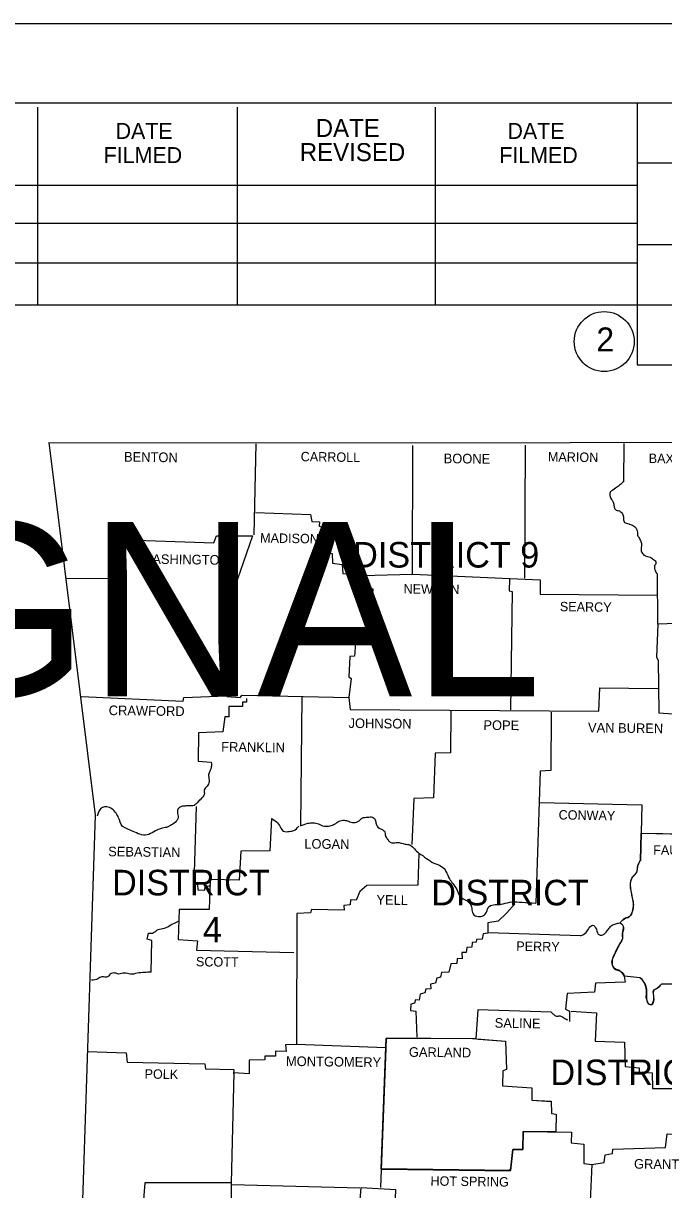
# Model space of a CAD drawing. Extents: x 646058 to 725608, y 1473014 to 1561048.
# Drawn here: x 700985 to 707716, y 1548787 to 1561048 of the extents above; entities that cross this region are included whole.
import ezdxf

# ---------------------------------------------------------------- set-up
doc = ezdxf.new("R2010")
doc.units = 0
for name, color, linetype in [('Default', 7, 'Continuous'), ('R_Border Notes', 7, 'Continuous'), ('R_Grid', 7, 'Continuous'), ('T_Vehicle Path Rt', 7, 'Continuous')]:
    doc.layers.add(name, color=color, linetype=linetype)

msp = doc.modelspace()

# ---------------------------------------------------------------- linework, layer by layer
at = {"layer": 'R_Border Notes'}
for p, q in [((648725, 1560211), (716704, 1560211)), ((701138, 1558087), (701138, 1560168)), ((703236, 1558087), (703236, 1560168)), ((705318, 1558087), (705318, 1560168)), ((707438, 1560211), (707438, 1557459)), ((716704, 1559579), (707438, 1559579)), ((699018, 1559347), (707438, 1559347)), ((699018, 1558947), (707438, 1558947)), ((716704, 1558719), (707438, 1558719)), ((699018, 1558530), (707438, 1558530)), ((716704, 1558087), (699018, 1558087)), ((707438, 1557459), (716704, 1557459))]:
    msp.add_line(p, q, dxfattribs=at)
msp.add_circle((707091, 1557703), 315, dxfattribs=at)
at = {"layer": 'R_Grid'}
msp.add_line((702045, 1555368), (702054, 1555377), dxfattribs=at)
for points in [[(701252, 1556640), (705063, 1556638), (708406, 1556646), (712352, 1556706), (714179, 1556749)], [(701252, 1556640), (701741, 1552724), (701529, 1546333)], [(703428, 1556627), (703407, 1555672)], [(703424, 1555905), (704002, 1555886), (704017, 1555811), (704097, 1555809), (704095, 1555762), (704152, 1555749), (704157, 1555492), (704230, 1555475), (704234, 1555374), (704337, 1555359), (704343, 1555265), (704547, 1555243), (705076, 1555256), (705080, 1556610)], [(706260, 1556614), (706254, 1555215)], [(707297, 1556631), (707292, 1556229)], [(708406, 1556631), (708411, 1556070), (708372, 1556068), (708378, 1555481), (708213, 1555458), (708226, 1555299), (708284, 1555226), (708280, 1555042), (707959, 1555029), (707948, 1554742), (707654, 1554731), (707642, 1554384), (707657, 1554354), (707665, 1553800), (708169, 1553765), (708162, 1552525), (708563, 1552512), (708563, 1551251), (708246, 1551227), (708222, 1550949), (707693, 1550947)], [(701439, 1555215), (701880, 1555213), (701893, 1555368), (702053, 1555368), (702068, 1555620), (702987, 1555588), (703015, 1555659), (703394, 1555661), (703204, 1555115), (703167, 1554241), (703137, 1554237), (703124, 1553973), (703264, 1553962), (703285, 1553984), (704407, 1553962), (704420, 1553836)], [(704542, 1555239), (704551, 1555111), (704660, 1555104), (704632, 1554708), (704583, 1554712), (704572, 1554648), (704517, 1554648), (704514, 1554539), (704478, 1554536), (704467, 1554397), (704416, 1554391), (704407, 1554179), (704431, 1554162), (704407, 1553962)], [(705076, 1555256), (706419, 1555198), (706416, 1555046), (707648, 1555036)], [(707654, 1554731), (707652, 1555263)], [(706095, 1555205), (706093, 1555083), (706123, 1555076), (706104, 1553832)], [(704420, 1553836), (707035, 1553817), (707046, 1554063), (707654, 1554057)], [(701595, 1553971), (702666, 1553922), (702672, 1553960), (703120, 1553980)], [(703332, 1553952), (703332, 1553911), (703287, 1553911), (703289, 1553868), (703146, 1553866), (703144, 1553759), (703103, 1553759), (703081, 1553600), (702827, 1553590), (702824, 1553290), (702961, 1553281)], [(703913, 1553971), (703898, 1552611)], [(705478, 1553819), (705476, 1553378), (705313, 1553376), (705298, 1552906), (705091, 1552900), (705067, 1552414)], [(706534, 1553806), (706528, 1553194), (706416, 1553185), (706371, 1551799)], [(702801, 1552814), (702777, 1552005), (702814, 1551994), (702820, 1551938), (702891, 1551934), (702897, 1551973), (702955, 1551983)], [(706410, 1552857), (707487, 1552832), (707472, 1552249)], [(703593, 1552688), (703576, 1552350), (703270, 1552347), (703253, 1552041), (702949, 1552048), (702940, 1551733), (702623, 1551731), (702612, 1551416), (702814, 1551403), (702805, 1551306), (703829, 1551279)], [(708222, 1550949), (707693, 1550947), (707645, 1550901), (707612, 1550885), (707609, 1550876), (707607, 1550854), (707614, 1550783), (707588, 1550728), (707558, 1550739), (707543, 1550772), (707532, 1550809), (707535, 1550849), (707534, 1550884), (707527, 1550923), (707510, 1550966), (707489, 1550998), (707476, 1551011), (707470, 1551015), (707301, 1551032), (707301, 1551039), (707288, 1551055), (707268, 1551075), (707246, 1551094), (707215, 1551100), (707196, 1551116), (707186, 1551128), (707178, 1551146), (707174, 1551163), (707172, 1551177), (707174, 1551197), (707180, 1551217), (707226, 1551317), (707286, 1551428), (707284, 1551456), (707282, 1551470), (707283, 1551479), (707293, 1551535), (707293, 1551546), (707292, 1551554), (707286, 1551567), (707281, 1551576), (707273, 1551583), (707260, 1551590), (707265, 1551602), (707286, 1551622), (707314, 1551643), (707333, 1551647), (707347, 1551650), (707361, 1551661), (707370, 1551672), (707388, 1551711), (707400, 1551766), (707397, 1551799), (707369, 1551948), (707366, 1551995), (707371, 1552029), (707388, 1552072), (707398, 1552084), (707434, 1552121), (707440, 1552154), (707442, 1552175), (707443, 1552192), (707468, 1552246), (707471, 1552248), (707473, 1552247), (707480, 1552534), (708563, 1552512)], [(707480, 1552534), (708162, 1552525)], [(705142, 1552326), (705131, 1551988), (704594, 1551985), (704523, 1551923), (704484, 1551829), (704424, 1551833), (704422, 1551780), (704354, 1551773), (704356, 1551724), (704015, 1551733), (704002, 1551696), (703861, 1551690), (703857, 1550313), (703739, 1550310), (703748, 1550240), (703636, 1550242), (703634, 1550191), (703523, 1550191), (703525, 1550152), (703360, 1550148), (703358, 1550004), (703197, 1550017), (703171, 1548858), (702263, 1548860), (702242, 1548593)], [(706151, 1551791), (706067, 1551698), (705975, 1551611), (705868, 1551593), (705868, 1551482), (705817, 1551476), (705808, 1551420), (705748, 1551416), (705744, 1551388), (705703, 1551386), (705701, 1551336), (705645, 1551334), (705641, 1551279), (705594, 1551279), (705596, 1551212), (705545, 1551217), (705540, 1551165), (705478, 1551161), (705459, 1551075), (705380, 1551069), (705371, 1551022), (705330, 1551009), (705318, 1550959), (705264, 1550949), (705268, 1550900), (705215, 1550895), (705204, 1550857), (705155, 1550842), (705144, 1550780), (705106, 1550782), (705095, 1550747), (705058, 1550737), (705056, 1550672), (705110, 1550664), (705121, 1550390)], [(702327, 1551073), (702334, 1551405), (702287, 1551420), (702302, 1551482)], [(706843, 1551454), (705870, 1551486)], [(707470, 1551015), (707301, 1551032), (707310, 1550970), (706999, 1550957), (706990, 1550865), (706701, 1550850), (706684, 1550685), (706727, 1550664), (706727, 1550555)], [(706534, 1550653), (705763, 1550677), (705742, 1550373), (704799, 1550379), (704795, 1550276)], [(706744, 1550662), (707008, 1550645), (706997, 1550349), (707305, 1550338), (707312, 1550081), (707457, 1550068), (707457, 1550026), (707594, 1550015), (707599, 1549850), (707909, 1549850), (707918, 1549687), (708207, 1549674), (708205, 1549368)], [(704748, 1549006), (704799, 1550379), (705742, 1550375)], [(704799, 1550366), (704812, 1550379)], [(705705, 1550375), (706054, 1550349), (706065, 1550051), (706024, 1550038), (706020, 1549880), (706329, 1549859), (706329, 1549728), (706534, 1549717), (706536, 1549587), (706586, 1549580), (706583, 1549394)], [(705770, 1550368), (706054, 1550347), (706065, 1550051), (706024, 1550036), (706020, 1549878), (706329, 1549856), (706329, 1549728), (706534, 1549715), (706536, 1549587), (706586, 1549580), (706583, 1549404)], [(701659, 1550240), (702066, 1550225), (702075, 1550126), (702891, 1550109), (702899, 1550058), (703197, 1550049), (703195, 1550004)], [(704795, 1550277), (703857, 1550314)], [(704795, 1550276), (704739, 1548809)], [(706583, 1549394), (706239, 1549398), (706236, 1549210), (706132, 1549210), (706106, 1548987), (704748, 1549006)], [(704756, 1549004), (706104, 1548985), (706132, 1549210), (706236, 1549210), (706239, 1549398), (706748, 1549392), (706744, 1549278), (706875, 1549267), (706875, 1549062), (706960, 1549053)], [(706960, 1549053), (707091, 1549072), (707102, 1549154), (707179, 1549167), (707183, 1549214), (707734, 1549231), (707753, 1549374), (708316, 1549366)], [(706087, 1548987), (706108, 1549010)], [(706960, 1549053), (706933, 1548436), (706911, 1548443), (706913, 1548124)], [(703171, 1548858), (703171, 1548546), (703223, 1548535), (703219, 1548244), (703529, 1548220), (703493, 1546663), (702850, 1546680)], [(703176, 1548841), (704523, 1548807)], [(704478, 1548376), (704474, 1548505), (704512, 1548507), (704536, 1548811), (704898, 1548788), (704889, 1548601), (705358, 1548576), (705360, 1548462), (705785, 1548436), (705857, 1548310), (705812, 1548252), (705834, 1548166), (707370, 1548109)]]:
    msp.add_lwpolyline(points, dxfattribs=at)
for points in [[(707292, 1556229), (707250, 1556192), (707211, 1556160), (707155, 1556119), (707149, 1556083), (707168, 1556044), (707185, 1556014), (707194, 1555972), (707209, 1555937), (707250, 1555922), (707282, 1555892), (707295, 1555849), (707299, 1555809), (707337, 1555790), (707378, 1555777), (707419, 1555749), (707438, 1555712), (707442, 1555667), (707460, 1555633), (707479, 1555590), (707483, 1555554), (707479, 1555520), (707487, 1555485), (707517, 1555453), (707573, 1555436), (707609, 1555413), (707635, 1555380), (707620, 1555340), (707622, 1555305), (707644, 1555263)], [(702961, 1553281), (702961, 1553232), (702942, 1553179), (702932, 1553136), (702938, 1553076), (702917, 1553029), (702887, 1552990), (702887, 1552943), (702850, 1552894), (702814, 1552857), (702779, 1552827), (702722, 1552821), (702672, 1552819), (702623, 1552802), (702604, 1552767), (702612, 1552714), (702593, 1552660), (702544, 1552622), (702490, 1552596), (702435, 1552585), (702355, 1552549), (702285, 1552517), (702210, 1552523), (702139, 1552553), (702075, 1552581), (702025, 1552609), (701987, 1552697), (701959, 1552744), (701916, 1552791), (701861, 1552810), (701816, 1552806), (701762, 1552714)], [(703593, 1552688), (703645, 1552654), (703685, 1552600), (703720, 1552555), (703780, 1552553), (703827, 1552562), (703880, 1552609)], [(703898, 1552611), (703975, 1552639), (704030, 1552643), (704088, 1552632), (704146, 1552609), (704210, 1552613), (704257, 1552630), (704304, 1552660), (704356, 1552671), (704405, 1552660), (704457, 1552647), (704514, 1552664), (704547, 1552694), (704604, 1552703), (704654, 1552703), (704688, 1552664), (704696, 1552622), (704739, 1552581), (704780, 1552555), (704793, 1552506), (704814, 1552470), (704834, 1552446), (704866, 1552433), (704917, 1552437), (704996, 1552420), (705050, 1552410), (705097, 1552369), (705142, 1552326)], [(705142, 1552326), (705223, 1552270), (705300, 1552221), (705382, 1552185), (705427, 1552133), (705465, 1552054), (705500, 1552005), (705540, 1551943), (705573, 1551874), (705622, 1551838), (705673, 1551803), (705699, 1551746), (705712, 1551686), (705767, 1551658), (705821, 1551668), (705853, 1551705), (705881, 1551765), (705945, 1551784), (706027, 1551793), (706121, 1551812), (706226, 1551808), (706371, 1551799)], [(707472, 1552249), (707442, 1552195), (707430, 1552125), (707391, 1552080), (707367, 1552028), (707365, 1551960), (707376, 1551898), (707389, 1551840), (707397, 1551784), (707387, 1551716), (707357, 1551658), (707310, 1551641), (707265, 1551602)], [(702302, 1551482), (702353, 1551489), (702402, 1551521), (702469, 1551536), (702535, 1551570), (702617, 1551608)], [(706843, 1551454), (706900, 1551489), (706933, 1551538), (706969, 1551568), (707008, 1551525), (707040, 1551465), (707076, 1551465), (707121, 1551508), (707149, 1551544), (707183, 1551572), (707222, 1551585), (707262, 1551589), (707292, 1551544), (707282, 1551474), (707282, 1551426), (707256, 1551377), (707228, 1551326), (707198, 1551266), (707175, 1551204), (707179, 1551142), (707211, 1551101), (707250, 1551090), (707301, 1551039)], [(702327, 1551073), (702259, 1551071), (702182, 1551062), (702111, 1551052), (702047, 1551064), (701989, 1551054), (701948, 1551064), (701899, 1551052), (701871, 1551024), (701811, 1551024), (701768, 1551004), (701702, 1550989)], [(707470, 1551015), (707511, 1550962), (707535, 1550891), (707535, 1550812), (707554, 1550745), (707592, 1550732), (707614, 1550788), (707609, 1550844), (707609, 1550878), (707650, 1550906), (707693, 1550947)], [(706710, 1550568), (706665, 1550591), (706631, 1550612), (706592, 1550608), (706562, 1550627), (706534, 1550653)]]:
    msp.add_spline(points, degree=3, dxfattribs=at)
at = {"layer": 'T_Vehicle Path Rt'}
msp.add_line((646059, 1561048), (717726, 1561048), dxfattribs=at)
msp.add_lwpolyline([(646058, 1561048), (717726, 1561048), (717726, 1515181), (646058, 1515181)], close=True, dxfattribs=at)

# ---------------------------------------------------------------- texts
at = {"layer": 'Default'}
msp.add_text('HWY. 18 QUALITY WAY SIGNAL ', height=1831.35, dxfattribs=at).set_placement((669557, 1553974))
at = {"layer": 'R_Border Notes'}
for s, height, p in [('DATE', 189, (704058, 1559854)), ('DATE', 168.1, (701955, 1559833)), ('DATE', 168.1, (706074, 1559833)), ('REVISED', 189, (703890, 1559600)), ('FILMED', 168.1, (701830, 1559579)), ('FILMED', 168.1, (705988, 1559579)), ('2', 252, (707008, 1557599))]:
    msp.add_text(s, height=height, rotation=360, dxfattribs=at).set_placement(p)
at = {"layer": 'R_Grid'}
for s, height, rotation, p in [('BENTON', 101.3, 359.2527, (702043, 1556441)), ('CARROLL', 99, 359.1481, (703900, 1556445)), ('BOONE', 101.3, 359.4001, (705403, 1556424)), ('MARION', 99, 359.1854, (706498, 1556443)), ('BAXTER', 99, 359.2559, (707558, 1556426)), ('MADISON', 99, 359.0906, (703473, 1555590)), ('WASHINGTON', 101.3, 359.232, (702212, 1555368)), ('NEWTON', 99, 359.2717, (704981, 1555055)), ('SEARCY', 98.9, 359.2527, (706624, 1554868)), ('CRAWFORD', 101.3, 359.2771, (701882, 1553776)), ('JOHNSON', 101.3, 359.3514, (704403, 1553641)), ('POPE', 101.3, 359.6155, (705821, 1553620)), ('VAN BUREN', 101.3, 359.3508, (706920, 1553594)), ('FRANKLIN', 101.3, 359.1815, (703064, 1553393)), ('CONWAY', 98.9, 359.0371, (706611, 1552679)), ('LOGAN', 101.3, 359.3969, (703938, 1552373)), ('FAULKNER', 99, 359.2486, (707605, 1552309)), ('SEBASTIAN', 101.3, 359.2816, (701876, 1552292)), ('YELL', 101.3, 359.1987, (704696, 1551784)), ('PERRY', 99, 359.0858, (706166, 1551298)), ('SCOTT', 99, 359.4063, (702799, 1551135)), ('SALINE', 101.3, 359.1491, (705939, 1550490)), ('GARLAND', 101.3, 359.3658, (705037, 1550184)), ('MONTGOMERY', 101.3, 359.2944, (703745, 1550088)), ('POLK', 98.9, 359.2152, (702259, 1549955)), ('GRANT', 101.3, 359.4032, (707404, 1549008)), ('HOT SPRING', 99, 359.2216, (705264, 1548830))]:
    msp.add_text(s, height=height, rotation=rotation, dxfattribs=at).set_placement(p)
for s, height, p in [('DISTRICT 9', 268.6, (704452, 1555327)), ('DISTRICT', 268.6, (701918, 1551881)), ('DISTRICT', 268.6, (705273, 1551776)), ('4', 269, (702872, 1551386)), ('DISTRICT 6', 268.6, (706526, 1549886))]:
    msp.add_text(s, height=height, dxfattribs=at).set_placement(p)

doc.saveas('drawing.dxf')
